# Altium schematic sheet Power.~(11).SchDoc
size A4; SheetNumber: 2; SheetTotal: 4
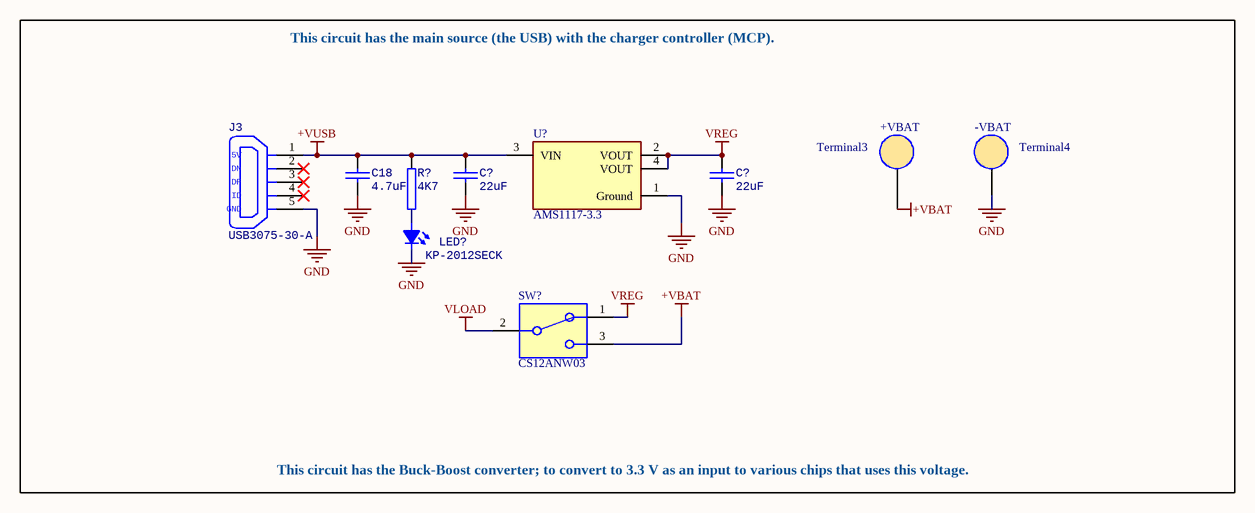
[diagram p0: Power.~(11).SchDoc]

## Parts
(Parts that share a designator on the sheet are numbered #1, #2 ... from top to bottom, then left to right.)
+VBAT  Terminal3  [test_point]
-VBAT  Terminal4  [test_point]
C18  4.7uF  [C0603]
C?#1  22uF  [C0603]
C?#2  22uF  [C0603]
J3  USB3075-30-A  [USB3075-30-a]
LED?  KP-2012SECK  [LED_0805]
R?  4K7  [R0603]
SW?  CS12ANW03  [CS12ANW03]
U?  AMS1117-3.3  [FP-AMS1117-IPC_C]

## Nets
+VBAT: +VBAT.?1 SW?.3(NO1)
+VUSB: C18.2 C?#1.2 J3.1(P1) R?.2 U?.3(VIN)
GND: -VBAT.?1 C18.1 C?#1.1 C?#2.1 J3.5(GND) LED?.K U?.1(Ground)
VLOAD: SW?.2(COM1)
VREG: C?#2.2 SW?.1(NC1) U?.2(VOUT) U?.4(VOUT)
NetLED?_A: LED?.A R?.1

Not connected (* = marked no-connect by the designer): J3 2(P2)* 3(P3)* 4(P4)*

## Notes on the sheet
- This circuit has the main source (the USB) with the charger controller (MCP).
- This circuit has the Buck-Boost converter; to convert to 3.3 V as an input to various chips that uses this voltage.

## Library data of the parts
+VBAT -VBAT = Component_1
C18 C?#1 C?#2 = 06035C103KAT4A: CAP CER 10nF 50V X7R 10% 0603; Manufacturer 1: Kyocera AVX
J3 = USB3075-30-A: CON RCPT MICRO USB B SMT; Manufacturer: Global Connector Technology; Gender: Receptacle; Number of Contacts: 5; USB Standard: USB 2.0
LED? = KP-2012SECK: LED ORANGE 180MCD 601NM 0805; Manufacturer: Kingbright; Lens Colour: Clear; Luminous Intensity: 250mcd; Viewing Angle: 120°; Forward Voltage: 2.5V; Forward Current: 20mA; Lens Style: Rectangular; Number of LEDs: 1
R? = CRGCQ0603J4K7: RES 4K7 1% 0603
SW? = CS12ANW03: SW SLIDE SPDT TH
U? = CMP-209535-000001-1: LDO Voltage Regulators 1A, 3.3V; Manufacturer: Advanced Monolithic Systems; Dropout Voltage: 1.1V; Output Type: Fixed; Nominal Supply Current: 5mA; Max Power Dissipation: 1.2W; Max Supply Voltage: 15V; Number Of Outputs: 1; Standoff Height: 0.64mm; Max Junction Temp: +125°C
